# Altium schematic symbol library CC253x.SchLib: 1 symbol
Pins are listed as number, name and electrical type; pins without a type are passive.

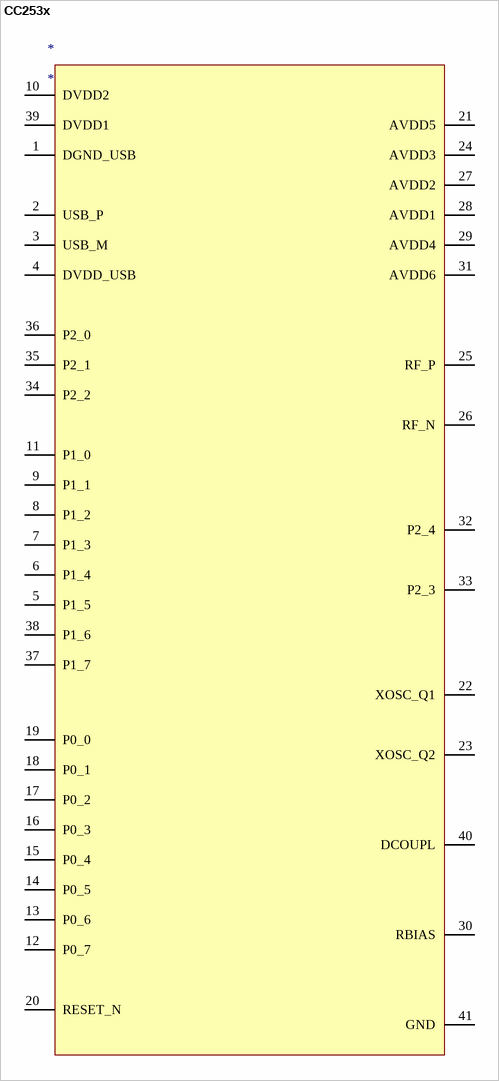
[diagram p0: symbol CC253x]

## CC253x
designator *
footprint CC253x
pins: 1 DGND_USB, 2 USB_P, 3 USB_M, 4 DVDD_USB, 5 P1_5, 6 P1_4, 7 P1_3, 8 P1_2, 9 P1_1, 10 DVDD2, 11 P1_0, 12 P0_7, 13 P0_6, 14 P0_5, 15 P0_4, 16 P0_3, 17 P0_2, 18 P0_1, 19 P0_0, 20 RESET_N, 21 AVDD5, 22 XOSC_Q1, 23 XOSC_Q2, 24 AVDD3, 25 RF_P, 26 RF_N, 27 AVDD2, 28 AVDD1, 29 AVDD4, 30 RBIAS, 31 AVDD6, 32 P2_4, 33 P2_3, 34 P2_2, 35 P2_1, 36 P2_0, 37 P1_7, 38 P1_6, 39 DVDD1, 40 DCOUPL, 41 GND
